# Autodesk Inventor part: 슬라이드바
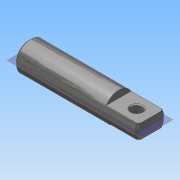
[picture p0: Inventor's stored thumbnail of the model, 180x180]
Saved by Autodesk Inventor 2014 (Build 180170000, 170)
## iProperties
Created: 2015-12
Part Number: 슬라이드바
Material: 스테인리스강
Document SubType Name: Modeling
Designer: mduedu
Density: 8.08 g/cm^3
Appearance: 반광택
Author: mduedu
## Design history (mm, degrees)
sketch "스케치1"
  geometry: L1 (-34, 0)-(34, 0); L2 (-34, 0)-(-34, 8); L3 (-34, 8)-(34, 8); L4 (34, 8)-(34, 0); 2 further points
  constraints: 8 end point, 2 perpendicular, 1 coincident, 1 horizontal, 1 midpoint, 1 vertical
  dimensions: "d0" = 68 distance of L2.end L3.end; "d2" = 16 diameter of L3 L1
revolve "회전1" sketch "스케치1" stored, may be unused: angle "d3" = 90 deg
sketch "스케치2"
  geometry: L1 (34, -8)-(34, 8) reference; L2 (0, 0)-(34, 0); L3 (34, 4)-(16, 4); L4 (16, 4)-(16, 8); L5 (16, 8)-(34, 8); L6 (34, 8)-(34, 4); L7 (-34, 8)-(34, 8) reference
  constraints: 10 end point, 2 parallel, 1 collinear, 1 horizontal, 1 midpoint, 1 perpendicular, 1 point on line
  dimensions: "d4" = 18 distance of L4.end L5.end; "d6" = 4 distance between parallel lines of L3 L2
extrude "돌출1" cut sketch "스케치2" stored distance "d8" = 10; taper "d9" = 0 deg
sketch "스케치3"
  geometry: L1 (0, 0)-(0, -13.856) reference; 2 further points
  constraints: 1 horizontal alignment
  dimensions: "d10" = 10 distance from line of point (10, -6.928) L1
hole "구멍1" sketch "스케치3" at (10, -6.928) diameter "d11" = 6; stored, may be unused: countersink angle "d15" = 90 deg, drill point angle "d17" = 118 deg; dims "d12" = 6, "d13" = 4, "d14" = 2, "d16" = 8
chamfer "모따기1" distance "d18" = 0.5; stored, may be unused: second distance "d19" = 2, angle "d20" = 45 deg
chamfer "모따기2" distance "d21" = 1; stored, may be unused: second distance "d22" = 2, angle "d23" = 45 deg
hole "구멍2" diameter "d26" = 4.917; stored, may be unused: countersink angle "d30" = 90 deg, drill point angle "d32" = 118 deg; dims "d24" = 10, "d25" = 10, "d27" = 12, "d28" = 4, "d29" = 2, "d31" = 13
chamfer "모따기3" distance "d33" = 1; stored, may be unused: second distance "d34" = 2, angle "d35" = 45 deg
node "작업 평면1"
node "솔리드1"
mirror "대칭1"
